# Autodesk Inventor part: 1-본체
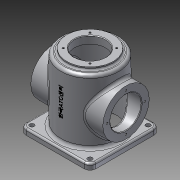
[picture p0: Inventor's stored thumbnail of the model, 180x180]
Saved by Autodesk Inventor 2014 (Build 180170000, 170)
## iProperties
Created: 2015-10
Part Number: 1-본체
Material: 알루미늄 6061
Document SubType Name: Modeling
Designer: Administrator
Density: 2.71 g/cm^3
Appearance: 알루미늄 - 평지
Mass: 985.994 g
Surface Area: 1037.35 cm^2
Volume: 363.836 cm^3
Author: Administrator
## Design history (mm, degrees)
sketch "스케치1"
  geometry: L1 (50, -50)-(0, -50); L2 (0, -50)-(0, 60); L3 (0, 60)-(50, 60); L4 (50, 60)-(50, -50); L5 (0, 60)-(40, 60); L6 (40, 60)-(40, 65); L7 (40, 65)-(0, 65); L8 (0, 65)-(0, 60); L9 (0, -50)-(45, -50); L10 (45, -50)-(45, 52); L11 (45, 52)-(0, 52); L12 (0, 52)-(0, -50); 1 further point
  constraints: 24 end point, 6 parallel, 3 horizontal, 3 perpendicular, 1 point on line
  dimensions: "d0" = 110 distance of L3.end L1.start; "d1" = 5 distance of L5.end L6.end; "d2" = 80 diameter of L6 L2; "d3" = 100 diameter of L4 L2; "d4" = 50 distance from line of point (0, 0) L1; "d5" = 102 distance of L9.end L10.end; "d6" = 90 diameter of L10 L2
revolve "회전1" sketch "스케치1" stored, may be unused: angle "d7" = 90 deg
sketch "스케치2"
  geometry: L1 (-60, -60)-(60, -60); L2 (60, -60)-(60, 60); L3 (60, 60)-(-60, 60); L4 (-60, 60)-(-60, -60); C1 r 45 at (0, 0) reference; 3 further points
  constraints: 8 end point, 2 midpoint, 2 parallel, 1 horizontal, 1 horizontal alignment, 1 perpendicular, 1 vertical alignment
  dimensions: "d8" = 120 distance between parallel lines of L3 L1; "d9" = 120 distance between parallel lines of L2 L4 (= d8)
extrude "돌출1" join sketch "스케치2" distance "d10" = 10; taper "d11" = 0 deg
node "작업 평면1"
sketch "스케치3"
  geometry: L1 (60, -60)-(-60, -60) reference; C1 r 40 at (0, 0); 1 further point
  constraints: 1 centre point, 1 coincident
  dimensions: "d13" = 60 distance from line of L1 C1.centre; "d14" = 80 diameter of C1
extrude "돌출2" join sketch "스케치3" stored distance "d15" = 0; taper "d16" = 0 deg
hole "구멍1" diameter "d19" = 54; stored, may be unused: countersink angle "d23" = 90 deg, drill point angle "d25" = 118 deg; dims "d17" = 10, "d18" = 10, "d20" = 6, "d21" = 4, "d22" = 2, "d24" = 8
hole "구멍2" diameter "d28" = 54; stored, may be unused: countersink angle "d32" = 90 deg, drill point angle "d34" = 118 deg; dims "d26" = 10, "d27" = 10, "d29" = 6, "d30" = 4, "d31" = 2, "d33" = 8
sketch "스케치4"
  geometry: L1 (0, 0)-(-32.5, 0)
  constraints: 2 end point, 1 horizontal
  dimensions: "d35" = 32.5 distance of L1.start L1.end
hole "구멍3" sketch "스케치4" at (-32.5, 0) diameter "d36" = 3.242; stored, may be unused: countersink angle "d40" = 90 deg, drill point angle "d42" = 118 deg; dims "d37" = 8, "d38" = 4, "d39" = 2, "d41" = 10
sketch "스케치5"
  geometry: L1 (0, 0)-(32.5, 0)
  constraints: 2 end point, 1 horizontal
  dimensions: "d46" = 32.5 distance of L1.start L1.end
hole "구멍4" sketch "스케치5" at (32.5, 0) diameter "d47" = 3.242; stored, may be unused: countersink angle "d51" = 90 deg, drill point angle "d53" = 118 deg; dims "d48" = 8, "d49" = 4, "d50" = 2, "d52" = 10
sketch "스케치6"
  geometry: L1 (0, 0)-(22.981, -22.981); L2 (0, -84)-(0, 84) reference
  constraints: 2 end point
  dimensions: "d92" = 45 deg angle of L2 L1; "d93" = 32.5 distance of L1.start L1.end
hole "구멍5" sketch "스케치6" at (22.981, -22.981) diameter "d58" = 3.242; stored, may be unused: countersink angle "d62" = 90 deg, drill point angle "d64" = 118 deg; dims "d59" = 8, "d60" = 4, "d61" = 2, "d63" = 10
sketch "스케치7"
  geometry: L1 (-50, -50)-(50, -50); L2 (50, -50)-(50, 50); L3 (50, 50)-(-50, 50); L4 (-50, 50)-(-50, -50); 3 further points
  constraints: 8 end point, 2 midpoint, 2 parallel, 1 horizontal, 1 horizontal alignment, 1 perpendicular, 1 vertical alignment
  dimensions: "d68" = 100 distance between parallel lines of L2 L4; "d69" = 100 distance between parallel lines of L3 L1 (= d68)
hole "구멍6" sketch "스케치7" at (0, 0), (-50, -50), (50, 50), (50, -50), (-50, 50) diameter "d70" = 8; stored, may be unused: countersink angle "d74" = 90 deg, drill point angle "d76" = 118 deg; dims "d71" = 8, "d72" = 4, "d73" = 2, "d75" = 10
chamfer "모따기1" distance "d77" = 3; stored, may be unused: second distance "d78" = 2, angle "d79" = 45 deg
fillet "모깎기1" dims "d80" = 5
chamfer "모따기2" distance "d81" = 1; stored, may be unused: second distance "d82" = 2, angle "d83" = 45 deg
fillet "모깎기2" dims "d84" = 3
fillet "모깎기3" dims "d85" = 10
fillet "모깎기4" dims "d86" = 3
node "작업 평면3"
  node "작업 평면2"
sketch "스케치8"
  geometry: L1 (-4.139, 2.368)-(-4.139, 7.632); L2 (-4.139, 7.632)-(4.139, 7.632); L3 (4.139, 7.632)-(4.139, 2.368); L4 (4.139, 2.368)-(-4.139, 2.368); L5 (50, -65)-(-50, -65) reference; 3 further points
  constraints: 2 midpoint, 1 vertical, 1 vertical alignment, 2 other
  dimensions: "d88" = 70 distance from line of point (4.139, 5) L5
feature "엠보싱1" sketch "스케치8" dims "d0" = 110, "d1" = 5, "d2" = 80, "d3" = 100, "d4" = 50, "d5" = 102, "d6" = 90, "d89" = 0.5, "d90" = 0
node "솔리드1"
mirror "대칭1"
pattern_circular "원형 패턴1" dims angle "d44" = 360 deg
pattern_circular "원형 패턴2" dims angle "d55" = 360 deg
pattern_circular "원형 패턴3" dims angle "d66" = 360 deg
other parameters: "d12" = 62, "d87" = 0.5
